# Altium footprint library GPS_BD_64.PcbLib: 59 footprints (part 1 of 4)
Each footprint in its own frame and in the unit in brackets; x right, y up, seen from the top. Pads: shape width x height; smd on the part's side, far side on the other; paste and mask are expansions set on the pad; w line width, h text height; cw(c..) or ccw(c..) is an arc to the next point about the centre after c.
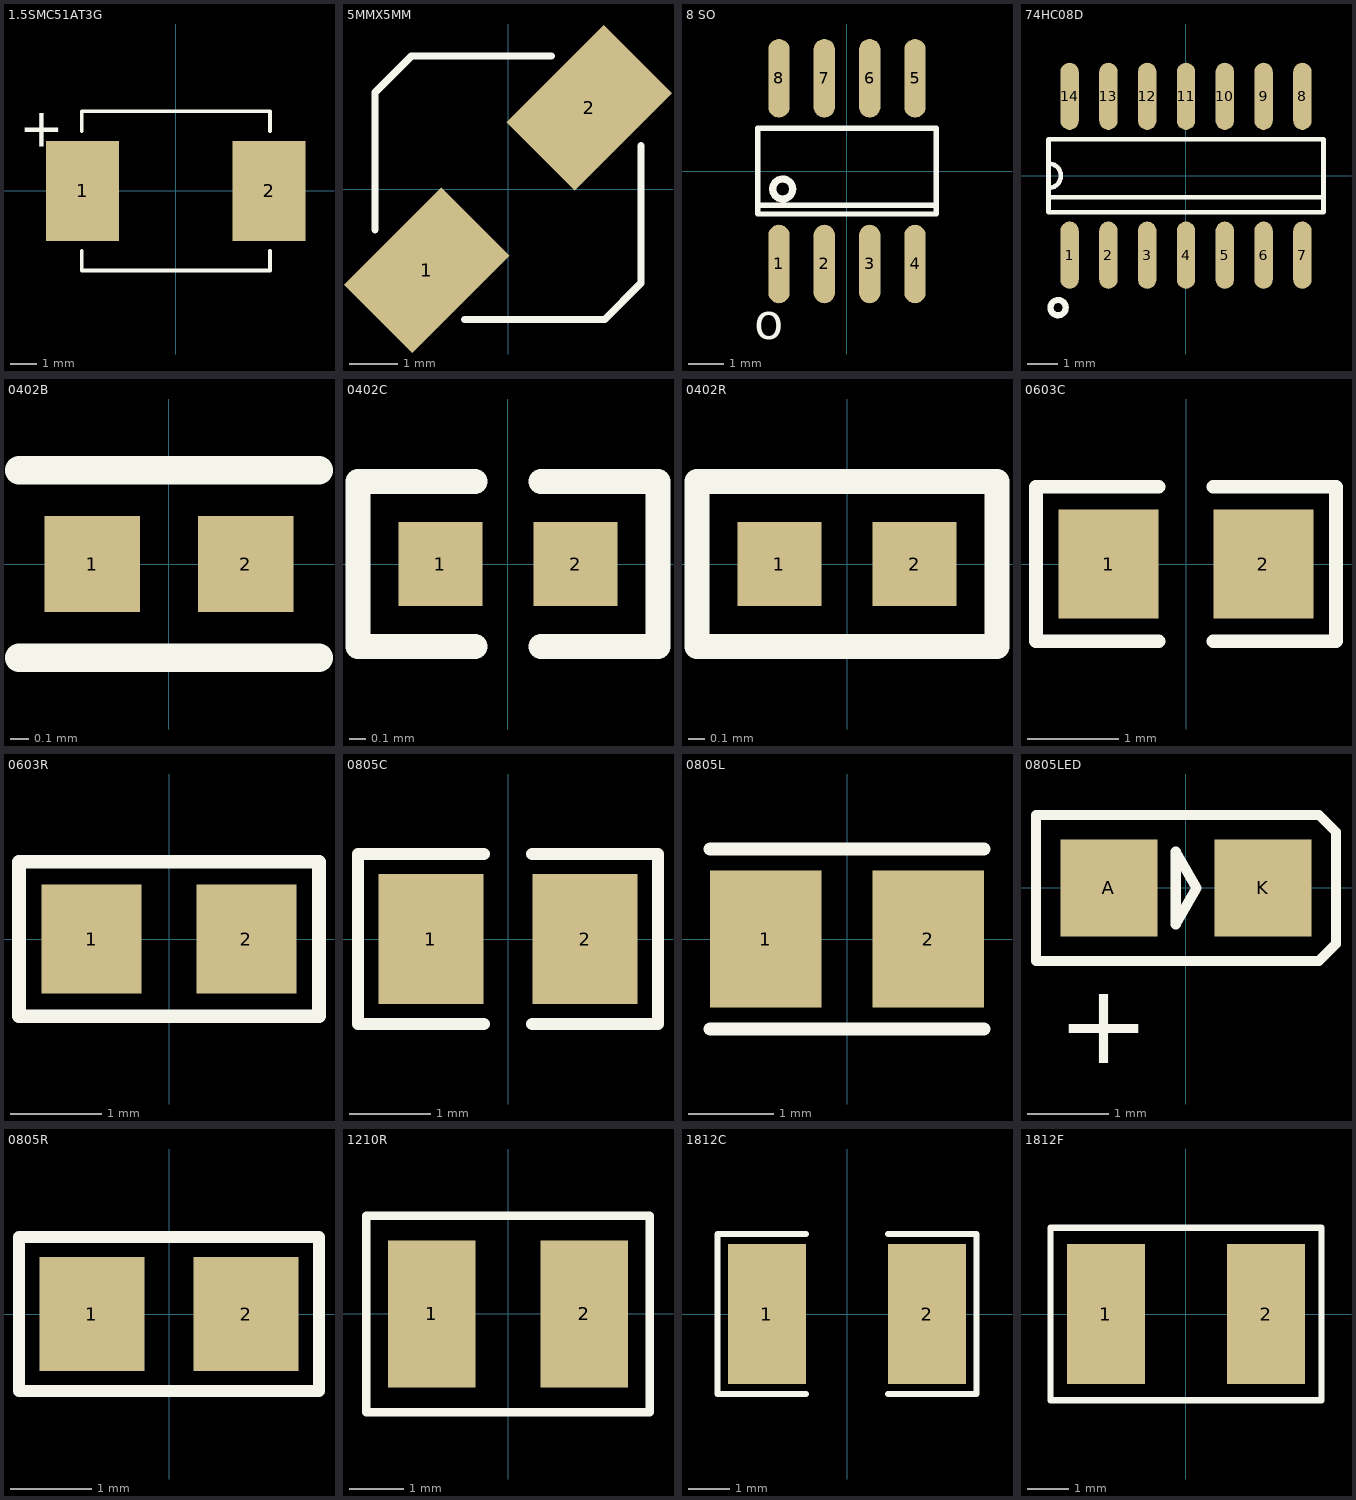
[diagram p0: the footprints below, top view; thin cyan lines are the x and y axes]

## 1.5SMC51AT3G [mil]
height 57.09
pads (2):
  rect 110x150 smd: 1(-140.5,0) 2(140.5,0)
Top Overlay:
  lines w5.91: -141.73,-90.55 -141.73,-120.08 141.73,-120.08 141.73,-90.55 ; -141.73,90.55 -141.73,120.08 141.73,120.08 141.73,90.55
  text "+" at -236.22,66.93 h59.06

## 5MMX5MM [mm]
height 1.45
pads (2):
  rect 2.85x2 smd rot 45: 1(-1.679,-1.679) 2(1.679,1.679)
Top Overlay:
  lines w0.15: -2.75,-0.85 -2.75,2 -2,2.75 0.9,2.75 ; -0.9,-2.7 2,-2.7 2.75,-1.95 2.75,0.9

## 8 SO [mm]
height 1.45
pads (8):
  oval 0.6x2.2 smd: 1(-1.905,-2.6) 2(-0.635,-2.6) 3(0.635,-2.6) 4(1.905,-2.6) 5(1.905,2.6) 6(0.635,2.6) 7(-0.635,2.6) 8(-1.905,2.6)
Top Overlay:
  circle w0.2: c-1.8,-0.5 r0.28
  lines w0.15: -2.5,-0.95 2.5,-0.95 ; -2.5,-1.2 2.5,-1.2 2.5,1.2 -2.5,1.2 -2.5,-0.8 -2.5,-1.2
  text "o" at -2.6,-4.7 h0.98

## 74HC08D [mm]
height 11
pads (14):
  oval 0.6x2.2 smd: 1(-3.81,-2.6) 2(-2.54,-2.6) 3(-1.27,-2.6) 4(0,-2.6) 5(1.27,-2.6) 6(2.54,-2.6) 7(3.81,-2.6) 8(3.81,2.6) 9(2.54,2.6) 10(1.27,2.6) 11(0,2.6) 12(-1.27,2.6) 13(-2.54,2.6) 14(-3.81,2.6)
Top Overlay:
  circle w0.2: c-4.187,-4.318 r0.25
  lines w0.15: -4.5,-0.7 4.5,-0.7 ; -4.495,-0.4 ccw(c-4.495,0) -4.495,0.4 ; -4.5,-1.2 4.5,-1.2 4.5,1.2 -4.5,1.2 -4.5,-1.2

## 0402B [mm]
height 1.45
pads (2):
  rect 0.51x0.51 smd: 1(-0.41,0) 2(0.41,0)
Top Overlay:
  lines w0.15: -0.8,-0.5 0.8,-0.5 ; -0.8,0.5 0.8,0.5

## 0402C [mm]
height 1.45
pads (2):
  rect 0.51x0.51 smd: 1(-0.41,0) 2(0.41,0)
Top Overlay:
  lines w0.15: -0.2,-0.5 -0.91,-0.5 -0.91,0.5 -0.2,0.5 ; 0.2,-0.5 0.91,-0.5 0.91,0.5 0.2,0.5

## 0402R [mm]
height 1.45
pads (2):
  rect 0.51x0.51 smd: 1(-0.41,0) 2(0.41,0)
Top Overlay:
  lines w0.15: -0.91,-0.5 -0.91,0.5 0.91,0.5 0.91,-0.5 -0.91,-0.5

## 0603C [mm]
height 11
pads (2):
  rect 1.1x1.2 smd: 1(-0.85,0) 2(0.85,0)
Top Overlay:
  lines w0.15: -0.3,-0.85 -1.65,-0.85 -1.65,0.85 -0.3,0.85 ; 0.3,-0.85 1.65,-0.85 1.65,0.85 0.3,0.85

## 0603R [mm]
height 11
pads (2):
  rect 1.1x1.2 smd: 1(-0.85,0) 2(0.85,0)
Top Overlay:
  lines w0.15: -1.65,-0.85 -1.65,0.85 1.65,0.85 1.65,-0.85 -1.65,-0.85

## 0805C [mm]
height 1.45
pads (2):
  rect 1.3x1.6 smd: 1(-0.95,0) 2(0.95,0)
Top Overlay:
  lines w0.15: -0.3,-1.05 -1.85,-1.05 -1.85,1.05 -0.3,1.05 ; 0.3,-1.05 1.85,-1.05 1.85,1.05 0.3,1.05

## 0805L [mm]
height 11
pads (2):
  rect 1.3x1.6 smd: 1(-0.95,0) 2(0.95,0)
Top Overlay:
  lines w0.15: -1.6,-1.05 1.6,-1.05 ; -1.6,1.05 1.6,1.05

## 0805LED [mm]
height 11
pads (2):
  rect 1.2x1.2 smd: A(-0.95,0) K(0.95,0)
Top Overlay:
  lines w0.127: -1.85,-0.9 -1.85,0.9 1.64,0.9 1.85,0.69 1.85,-0.69 1.64,-0.9 -1.85,-0.9 ; -0.127,-0.45 0.127,0 -0.127,0.45 -0.127,-0.45
  text "+" at -1.59,-2.159 h1

## 0805R [mm]
height 1.45
pads (2):
  rect 1.3x1.4 smd: 1(-0.95,0) 2(0.95,0)
Top Overlay:
  lines w0.15: -1.85,-0.95 -1.85,0.95 1.85,0.95 1.85,-0.95 -1.85,-0.95

## 1210R [mm]
pads (2):
  rect 1.6x2.7 smd: 1(-1.4,0) 2(1.4,0)
Top Overlay:
  lines w0.15: -2.6,-1.8 -2.6,1.8 2.6,1.8 2.6,-1.8 -2.6,-1.8

## 1812C [mm]
pads (2):
  rect 1.9x3.4 smd: 1(-1.95,0) 2(1.95,0)
Top Overlay:
  lines w0.15: -1,-1.95 -3.15,-1.95 -3.15,1.95 -1,1.95 ; 1,-1.95 3.15,-1.95 3.15,1.95 1,1.95

## 1812F [mm]
height 1.45
pads (2):
  rect 1.9x3.4 smd: 1(-1.95,0) 2(1.95,0)
Top Overlay:
  lines w0.15: -3.3,-2.1 -3.3,2.1 3.3,2.1 3.3,-2.1 -3.3,-2.1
